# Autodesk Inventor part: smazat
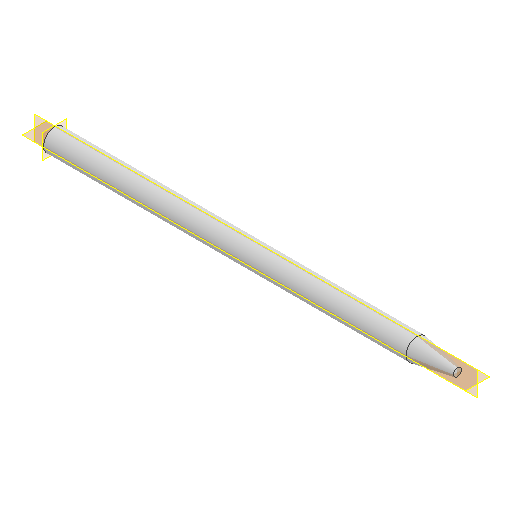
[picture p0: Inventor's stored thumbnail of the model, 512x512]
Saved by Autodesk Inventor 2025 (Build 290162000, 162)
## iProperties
Created: 2025-03
Part Number: smazat
Material: Generic
Document SubType Name: Modeling
Designer: dansp
Density: 1 g/cm^3
Appearance: Default
Author: dansp
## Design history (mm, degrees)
sketch "Sketch1"
  geometry: L1 (0, 3.3)-(0, -0.55) reference; L2 (-20, 0)-(120, 0) reference; L3 (0, 0)-(100, 0); L4 (100, 0)-(100, 2.75); L5 (100, 2.75)-(0, 2.75); L6 (0, 2.75)-(0, 0); L7 (100, 1)-(90, 2.75); 2 further points
  constraints: 10 end point, 2 parallel, 2 point on line, 1 horizontal, 1 perpendicular
  dimensions: "d0" = 5.5 diameter of L5 L2; "d1" = 10 distance from line of L7.end L4; "d2" = 1 distance from line of L3 L7.start; "d3" = 100 distance between parallel lines of L4 L1
revolve "Revolution1" sketch "Sketch1" stored, may be unused: angle "d4" = 90 deg
body "Solid1"
